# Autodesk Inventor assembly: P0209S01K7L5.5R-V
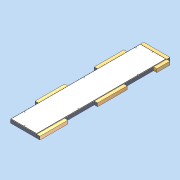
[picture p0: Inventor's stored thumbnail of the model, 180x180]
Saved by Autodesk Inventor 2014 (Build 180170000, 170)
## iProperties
Created: 2011-04
Part Number: P0209S01K7L5.5R-V
Document SubType Name: Assembly
Designer: david.appleford
Description: 0.5w x 2.25w 01 Panel - 7 Locks 5.5 Lugs RH
Mass: 30181.9 g
Surface Area: 43472.2 cm^2
Volume: 130143 cm^3
Density: 0.231913 g/cm^3
Cost Center: £131.00
Justset: False
Title: 0.5w x 2.25w 01 Panel - 7 Locks 5.5 Lugs RH
Author: david.appleford
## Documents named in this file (6)
- C:\Documents and Settings\david.appleford\Local Settings\My Documents\Vault\Production MkII\Virtual Elements\Virtual Walls\Virtual Timber + MgO\P0209S01K7L5.5R-V.iam
- C:\Documents and Settings\david.appleford\Local Settings\My Documents\Vault\Production MkII\VIRTUAL ELEMENTS\Virtual Lugs\Superceded Lugs\LA02C3V.ipt
- C:\Documents and Settings\david.appleford\Local Settings\My Documents\Vault\Production MkII\VIRTUAL ELEMENTS\Virtual Lugs\Superceded Lugs\LA02M3V.ipt
- C:\Documents and Settings\david.appleford\Local Settings\My Documents\Vault\Production MkII\Virtual Elements\Virtual Walls\Virtual Timber + MgO\P0209S01K7-V.ipt
- C:\Documents and Settings\david.appleford\Local Settings\My Documents\Vault\Production MkII\VIRTUAL ELEMENTS\Virtual Lugs\Superceded Lugs\LA01C3V.ipt
- C:\Documents and Settings\david.appleford\Local Settings\My Documents\Vault\Production MkII\VIRTUAL ELEMENTS\Virtual Lugs\Superceded Lugs\LA02E3V.ipt
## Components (7 placed, 5 different names)
1. P0209S01K7-V:1 — Mate:1, Flush:1, Flush:2, Mate:5, Mate:6, Flush:9, Flush:10, Mate:7, Flush:11, Mate:15, Flush:14, Flush:15, Mate:16, Flush:16, Flush:17
2. LA02C3V:1 — Mate:1, Flush:1, Flush:2, Mate:9, Mate:13
3. LA02M3V:5 — Mate:6, Flush:9, Mate:12
4. LA02M3V:2 — Mate:5, Flush:10, Mate:12, Mate:13
5. LA02M3V:4 — Mate:7, Flush:11, Mate:9
6. LA01C3V:1 — Mate:15, Flush:14, Flush:15
7. LA02E3V:1 — Mate:16, Flush:16, Flush:17
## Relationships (18: Mate 9, Flush 9)
- Mate:1: P0209S01K7-V:1 ↔ LA02C3V:1
- Flush:1: P0209S01K7-V:1 ↔ LA02C3V:1
- Flush:2: P0209S01K7-V:1 ↔ LA02C3V:1
- Mate:5: P0209S01K7-V:1 ↔ LA02M3V:2
- Mate:6: P0209S01K7-V:1 ↔ LA02M3V:5
- Flush:9: P0209S01K7-V:1 ↔ LA02M3V:5
- Flush:10: P0209S01K7-V:1 ↔ LA02M3V:2
- Mate:7: P0209S01K7-V:1 ↔ LA02M3V:4
- Flush:11: P0209S01K7-V:1 ↔ LA02M3V:4
- Mate:9: LA02C3V:1 ↔ LA02M3V:4
- Mate:12: LA02M3V:5 ↔ LA02M3V:2
- Mate:13: LA02C3V:1 ↔ LA02M3V:2
- Mate:15: P0209S01K7-V:1 ↔ LA01C3V:1
- Flush:14: P0209S01K7-V:1 ↔ LA01C3V:1
- Flush:15: P0209S01K7-V:1 ↔ LA01C3V:1
- Mate:16: P0209S01K7-V:1 ↔ LA02E3V:1
- Flush:16: P0209S01K7-V:1 ↔ LA02E3V:1
- Flush:17: P0209S01K7-V:1 ↔ LA02E3V:1
## Named parameters: t = 1 mm, Cl = 2 mm
